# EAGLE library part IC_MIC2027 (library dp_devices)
Quad USB Power Distribution Switch Mfr no: MIC2027-2YM MIC2027
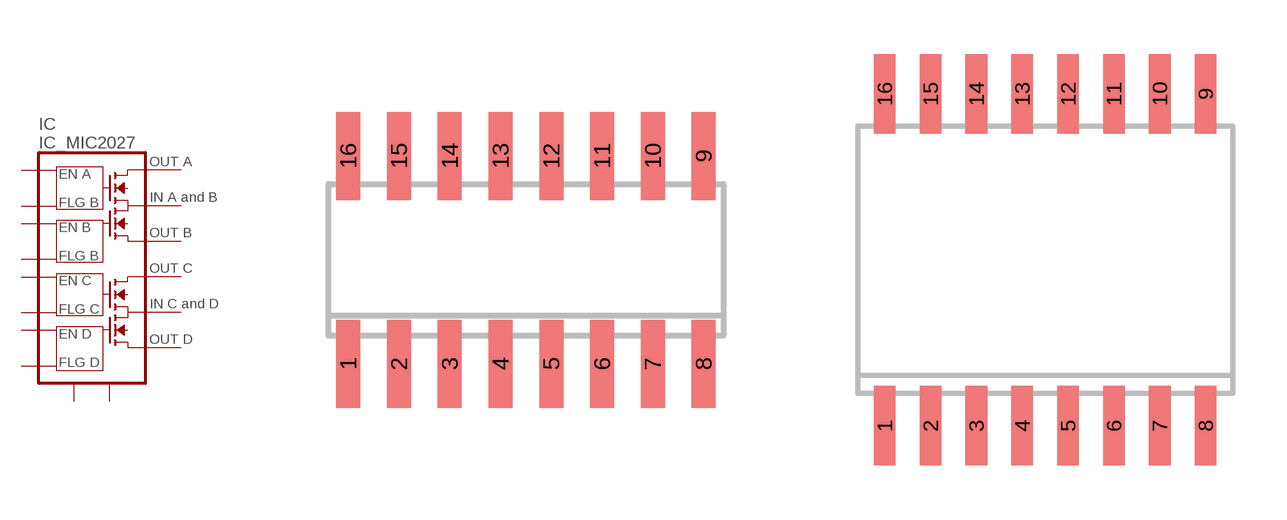
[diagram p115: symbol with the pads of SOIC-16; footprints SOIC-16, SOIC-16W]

Designator prefix IC

## IC_MIC2027-SOIC-16  [SOIC-16]
1  FLG_A  out
2  EN_A  in
3  OUT_A  out
4  GND  pwr
5  IN_CD  in
6  OUT_C  out
7  EN_C  in
8  FLG_C  out
9  FLG_D  out
10  EN_D  in
11  OUT_D  out
12  GND  pwr
13  IN_AB  in
14  OUT_B  out
15  EN_B  in
16  FLG_B  out

## IC_MIC2027-SOIC-16W  [SOIC-16W]
Pads as for SOIC-16

## Footprint SOIC-16 (pad centres in mm)
smd 0.6 x 2.2: 1 -4.445,-2.6; 2 -3.175,-2.6; 3 -1.905,-2.6; 4 -0.635,-2.6; 5 0.635,-2.6; 6 1.905,-2.6; 7 3.175,-2.6; 8 4.445,-2.6; 9 4.445,2.6; 10 3.175,2.6; 11 1.905,2.6; 12 0.635,2.6; 13 -0.635,2.6; 14 -1.905,2.6; 15 -3.175,2.6; 16 -4.445,2.6

## Footprint SOIC-16W (pad centres in mm)
smd 0.6 x 2.2: 1 -4.445,-4.6; 2 -3.175,-4.6; 3 -1.905,-4.6; 4 -0.635,-4.6; 5 0.635,-4.6; 6 1.905,-4.6; 7 3.175,-4.6; 8 4.445,-4.6; 9 4.445,4.6; 10 3.175,4.6; 11 1.905,4.6; 12 0.635,4.6; 13 -0.635,4.6; 14 -1.905,4.6; 15 -3.175,4.6; 16 -4.445,4.6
